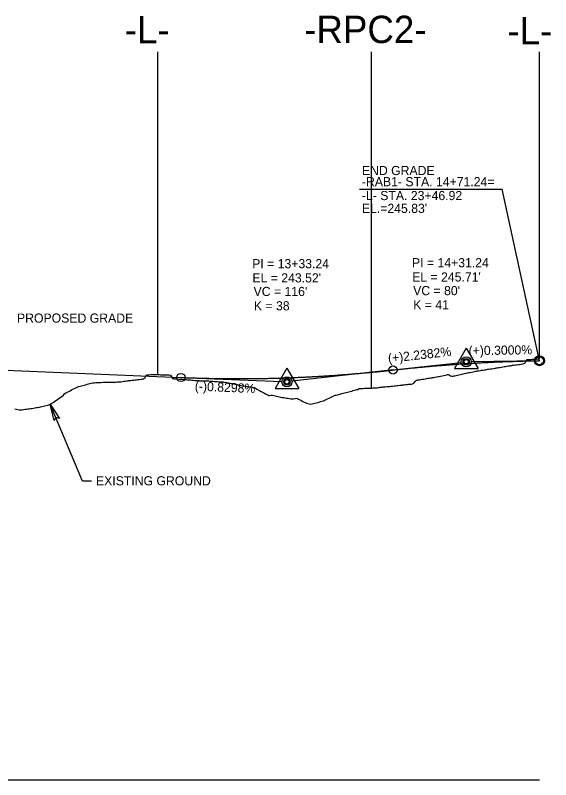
# Model space of a CAD drawing. Extents: x 2115752 to 2121174, y 562881 to 567245.
# Drawn here: x 2120307 to 2120599.7, y 565506.4 to 565924.5 of the extents above; entities that cross this region are included whole.
import ezdxf

# ---------------------------------------------------------------- set-up
doc = ezdxf.new("R2010")
doc.units = 0
for name, color, linetype in [('Exist Profile Cell', 7, 'Continuous'), ('Exist Vertical Profile Ground Line', 7, 'Continuous'), ('Prop PFL VPI Symbol CELL', 7, 'Continuous'), ('Prop Terminator CELL', 7, 'Continuous'), ('Prop Vertical Profile Curve Label', 7, 'Continuous'), ('Prop Vertical Profile Grade', 7, 'Continuous'), ('Prop Vertical Profile Grade Label', 7, 'Continuous'), ('Prop VPI Label', 7, 'Continuous'), ('Scratch_Level_1', 7, 'Continuous')]:
    doc.layers.add(name, color=color, linetype=linetype)

msp = doc.modelspace()

# ---------------------------------------------------------------- linework, layer by layer
at = {"layer": 'Exist Profile Cell'}
msp.add_line((2120122.31, 565506.42), (2120593.55, 565506.42), dxfattribs=at)
at = {"layer": 'Exist Vertical Profile Ground Line'}
for points in [[(2120553.44, 565728.76), (2120553.75, 565728.83), (2120554.21, 565728.91), (2120554.98, 565729.05), (2120555.75, 565729.19), (2120556.52, 565729.33), (2120557.29, 565729.5), (2120558.07, 565729.68), (2120558.9, 565729.84), (2120559.61, 565729.95), (2120560.38, 565730.07), (2120561.43, 565730.22), (2120561.92, 565730.31), (2120562.69, 565730.42), (2120563.46, 565730.54), (2120564.24, 565730.66), (2120565.19, 565730.85), (2120565.78, 565730.94), (2120566.67, 565731.08), (2120567.32, 565731.18), (2120568.38, 565731.33), (2120569.31, 565731.46), (2120569.64, 565731.51), (2120570, 565731.58), (2120570.41, 565731.64), (2120571.18, 565731.76), (2120571.95, 565731.88), (2120572.78, 565732.05), (2120573.49, 565732.17), (2120574.26, 565732.31), (2120575.07, 565732.45), (2120575.81, 565732.57), (2120576.58, 565732.7), (2120577.5, 565732.85), (2120578.12, 565732.94), (2120578.49, 565732.99), (2120578.89, 565733.04), (2120579.66, 565733.14), (2120580.43, 565733.23), (2120581.21, 565733.33), (2120582.12, 565733.45), (2120582.75, 565733.55), (2120583.52, 565733.67), (2120584.29, 565733.79), (2120584.64, 565733.85), (2120585.53, 565734.14), (2120585.83, 565734.62), (2120586.83, 565736.18), (2120587.38, 565736.21), (2120588.15, 565736.25), (2120588.92, 565736.29), (2120589.69, 565736.34), (2120590.46, 565736.38), (2120591.23, 565736.42), (2120592, 565736.46), (2120592.78, 565736.5), (2120593.55, 565736.54)], [(2120486.28, 565717.75), (2120487.05, 565717.95), (2120487.83, 565718.15), (2120488.6, 565718.35), (2120489.37, 565718.56), (2120490.15, 565718.77), (2120490.92, 565718.98), (2120491.7, 565719.19), (2120492.47, 565719.41), (2120493.24, 565719.63), (2120493.69, 565719.76), (2120494.02, 565719.9), (2120495.07, 565720.35), (2120495.57, 565720.38), (2120496.34, 565720.41), (2120497.11, 565720.44), (2120497.89, 565720.47), (2120498.9, 565720.52), (2120499.43, 565720.54), (2120499.84, 565720.56), (2120500.21, 565720.57), (2120500.64, 565720.57), (2120500.98, 565720.59), (2120501.84, 565720.63), (2120502.53, 565720.67), (2120503.55, 565720.73), (2120504.07, 565720.76), (2120504.84, 565720.82), (2120505.61, 565720.92), (2120506.08, 565720.98), (2120506.38, 565721.02), (2120507.16, 565721.13), (2120507.53, 565721.18), (2120507.93, 565721.21), (2120508.99, 565721.29), (2120509.47, 565721.32), (2120510.28, 565721.37), (2120511.01, 565721.44), (2120511.34, 565721.47), (2120511.78, 565721.51), (2120512.55, 565721.57), (2120512.99, 565721.61), (2120513.33, 565721.65), (2120514.1, 565721.74), (2120514.87, 565721.84), (2120515.79, 565721.95), (2120516.41, 565722.03), (2120517.18, 565722.12), (2120517.95, 565722.21), (2120518.31, 565722.26), (2120518.73, 565722.31), (2120519.55, 565722.42), (2120520.27, 565722.51), (2120521.11, 565722.6), (2120521.45, 565722.64), (2120521.81, 565722.67), (2120522.58, 565722.73), (2120523.61, 565722.82), (2120524.13, 565722.95), (2120524.9, 565723.27), (2120525.67, 565724.26), (2120526.44, 565724.96), (2120526.78, 565725.01), (2120527.21, 565725.07), (2120527.98, 565725.19), (2120528.75, 565725.31), (2120529.52, 565725.44), (2120530.3, 565725.56), (2120531.31, 565725.73), (2120531.84, 565725.81), (2120532.61, 565725.93), (2120533.38, 565726.05), (2120534.15, 565726.17), (2120534.92, 565726.29), (2120535.27, 565726.35), (2120535.7, 565726.42), (2120536.47, 565726.54), (2120537.24, 565726.69), (2120538.23, 565726.89), (2120538.78, 565726.99), (2120539.55, 565727.13), (2120540.32, 565727.3), (2120541.39, 565727.53), (2120542.13, 565727.7), (2120542.86, 565727.89), (2120543.41, 565728), (2120543.73, 565728.07), (2120544.38, 565727.7), (2120544.95, 565727.36), (2120545.72, 565727.09), (2120546.49, 565727.17), (2120546.91, 565727.27), (2120547.27, 565727.35), (2120548.04, 565727.52), (2120548.81, 565727.69), (2120549.58, 565727.87), (2120550.42, 565728.06), (2120551.26, 565728.26), (2120551.89, 565728.4), (2120552.67, 565728.58), (2120553.44, 565728.76)], [(2120340.08, 565720.75), (2120340.85, 565721.14), (2120341.63, 565721.5), (2120342.4, 565721.69), (2120343.17, 565721.88), (2120343.94, 565722.07), (2120344.72, 565722.26), (2120345.49, 565722.46), (2120346.26, 565722.65), (2120347.04, 565722.85), (2120347.81, 565723.04), (2120348.58, 565723.24), (2120349.43, 565723.46), (2120350.13, 565723.55), (2120351.07, 565723.6), (2120351.67, 565723.63), (2120352.45, 565723.66), (2120353.3, 565723.7), (2120353.99, 565723.72), (2120355.06, 565723.77), (2120355.54, 565723.78), (2120356.31, 565723.79), (2120357.14, 565723.8), (2120357.86, 565723.81), (2120358.73, 565723.83), (2120359.4, 565723.84), (2120360.18, 565723.86), (2120360.95, 565723.88), (2120361.72, 565723.89), (2120362.05, 565723.9), (2120362.79, 565723.93), (2120363.27, 565723.98), (2120364.04, 565724.04), (2120364.81, 565724.1), (2120365.59, 565724.21), (2120366.5, 565724.33), (2120367.13, 565724.41), (2120367.91, 565724.52), (2120368.68, 565724.63), (2120369.12, 565724.69), (2120369.52, 565724.75), (2120369.86, 565724.79), (2120370.22, 565724.82), (2120371, 565724.9), (2120371.77, 565724.97), (2120372.54, 565725.04), (2120373.32, 565725.12), (2120374.09, 565725.22), (2120374.86, 565725.32), (2120375.63, 565725.42), (2120376.41, 565725.53), (2120377.18, 565725.66), (2120378, 565726.45), (2120378.73, 565727.9), (2120379.5, 565727.91), (2120380.27, 565727.92), (2120381.05, 565727.94), (2120381.46, 565727.94), (2120381.82, 565727.95), (2120382.59, 565727.95), (2120383.36, 565727.96), (2120384.14, 565727.97), (2120385.18, 565727.99), (2120385.68, 565727.97), (2120386.46, 565727.93), (2120387.23, 565727.9), (2120388.29, 565727.86), (2120388.78, 565727.84), (2120389.55, 565727.81), (2120390.33, 565727.78), (2120391.1, 565727.76), (2120391.87, 565727.65), (2120393.03, 565725.8), (2120393.48, 565725.75), (2120393.81, 565725.73), (2120394.2, 565725.69), (2120394.97, 565725.63), (2120395.74, 565725.57), (2120396.52, 565725.51), (2120397.29, 565725.46), (2120398.06, 565725.4), (2120399.24, 565725.32), (2120399.61, 565725.3), (2120400.39, 565725.24), (2120401.16, 565725.19), (2120401.93, 565725.13), (2120402.87, 565725.04), (2120403.48, 565725), (2120404.3, 565724.93), (2120405.25, 565724.81), (2120406.26, 565724.71), (2120406.83, 565724.69), (2120407.35, 565724.67), (2120407.67, 565724.65), (2120408.12, 565724.62), (2120408.9, 565724.58), (2120409.67, 565724.54), (2120410.45, 565724.51), (2120411.22, 565724.47), (2120411.99, 565724.47), (2120412.77, 565724.47)], [(2120306.84, 565709.22), (2120307.62, 565709.07), (2120308.39, 565708.93), (2120309.16, 565708.79), (2120310.21, 565708.62), (2120310.71, 565708.7), (2120311.48, 565708.83), (2120312.36, 565708.98), (2120313.03, 565709.06), (2120313.8, 565709.16), (2120314.57, 565709.27), (2120315.35, 565709.38), (2120316.12, 565709.5), (2120316.89, 565709.62), (2120317.66, 565709.75), (2120318.44, 565709.89), (2120319.21, 565710.03), (2120319.98, 565710.18), (2120320.28, 565710.24), (2120320.76, 565710.34), (2120321.53, 565710.51), (2120322.3, 565710.69), (2120323.08, 565710.88), (2120323.85, 565711.07), (2120324.62, 565711.27), (2120325.39, 565711.47), (2120326.17, 565711.75), (2120326.94, 565712.26), (2120327.71, 565712.77), (2120328.49, 565713.29), (2120329.26, 565713.82), (2120330.03, 565714.35), (2120330.8, 565714.89), (2120331.58, 565715.44), (2120332.38, 565716.02), (2120333.12, 565716.62), (2120334.15, 565717.69), (2120334.67, 565718.03), (2120335.44, 565718.41), (2120336.22, 565718.8), (2120336.99, 565719.18), (2120337.76, 565719.57), (2120338.53, 565719.96), (2120339.31, 565720.35), (2120340.08, 565720.75)], [(2120412.77, 565724.47), (2120413.54, 565724.46), (2120414.47, 565724.37), (2120415.09, 565724.32), (2120415.86, 565724.26), (2120416.64, 565724.18), (2120416.99, 565724.14), (2120417.41, 565724.12), (2120418.18, 565724.07), (2120419.1, 565724.05), (2120420.05, 565724.01), (2120420.51, 565723.94), (2120420.82, 565723.89), (2120421.28, 565723.82), (2120422.05, 565723.69), (2120422.83, 565723.56), (2120423.75, 565723.4), (2120424.47, 565723.28), (2120425.2, 565723.13), (2120425.92, 565723.02), (2120427.06, 565722.82), (2120427.47, 565722.71), (2120427.82, 565722.62), (2120428.24, 565722.47), (2120429.02, 565722.21), (2120429.79, 565722.09), (2120430.56, 565721.97), (2120431.34, 565721.85), (2120432.11, 565721.74), (2120432.89, 565721.63), (2120433.66, 565721.52), (2120434.43, 565721.42), (2120435.21, 565721.32), (2120435.98, 565721.22), (2120436.76, 565721.13), (2120437.53, 565720.92), (2120438.3, 565720.5), (2120439.08, 565720.07), (2120439.85, 565719.64), (2120440.62, 565719.22), (2120441.4, 565718.8), (2120442.17, 565718.37), (2120442.95, 565717.95), (2120443.72, 565717.53), (2120444.49, 565717.11), (2120445.27, 565716.69), (2120445.59, 565716.51), (2120446.04, 565716.57), (2120446.81, 565716.68), (2120447.61, 565716.79), (2120448.36, 565716.6), (2120449.14, 565716.41), (2120449.91, 565716.22), (2120450.68, 565716.04), (2120451.46, 565715.86), (2120452.23, 565715.69), (2120453.01, 565715.52), (2120453.44, 565715.43), (2120453.78, 565715.37), (2120454.55, 565715.24), (2120455.33, 565715.11), (2120456.1, 565714.99), (2120456.87, 565714.87), (2120457.65, 565714.76), (2120458.42, 565714.65), (2120459.2, 565714.78), (2120459.97, 565714.91), (2120460.95, 565715.08), (2120461.52, 565714.77), (2120462.29, 565714.35), (2120463.07, 565713.93), (2120463.84, 565713.51), (2120464.61, 565713.09), (2120465.49, 565712.62), (2120466.16, 565712.42), (2120466.93, 565712.2), (2120467.71, 565711.99), (2120468.48, 565711.88), (2120469.26, 565711.98), (2120470.04, 565712.09), (2120470.8, 565712.29), (2120471.58, 565712.5), (2120472.35, 565712.72), (2120473.12, 565712.94), (2120473.9, 565713.17), (2120474.67, 565713.4), (2120475.45, 565713.64), (2120476.22, 565713.99), (2120476.99, 565714.34), (2120477.77, 565714.7), (2120478.54, 565715.06), (2120479.32, 565715.43), (2120480.09, 565715.81), (2120480.86, 565716.19), (2120481.83, 565716.67), (2120482.41, 565716.78), (2120483.18, 565716.94), (2120483.96, 565717.15), (2120484.93, 565717.42), (2120485.51, 565717.56), (2120486.28, 565717.75)]]:
    msp.add_lwpolyline(points, dxfattribs=at)
at = {"layer": 'Prop PFL VPI Symbol CELL'}
for p, q in [((2120553.54, 565742.45), (2120547.09, 565731.25)), ((2120553.54, 565742.45), (2120560.04, 565731.25)), ((2120455.54, 565731.48), (2120449.09, 565720.28)), ((2120455.54, 565731.48), (2120462.04, 565720.28)), ((2120547.09, 565731.25), (2120560.04, 565731.25)), ((2120449.09, 565720.28), (2120462.04, 565720.28))]:
    msp.add_line(p, q, dxfattribs=at)
for centre, radius in [((2120553.55, 565734.97), 1.75), ((2120553.55, 565734.97), 1.2), ((2120455.55, 565724), 1.75), ((2120455.55, 565724), 1.2)]:
    msp.add_circle(centre, radius, dxfattribs=at)
at = {"layer": 'Prop Terminator CELL'}
msp.add_lwpolyline([(2120328.2, 565702.85), (2120326.17, 565711.75), (2120331.13, 565704.01), (2120329.21, 565704.46)], close=True, dxfattribs=at)
at = {"layer": 'Prop Vertical Profile Curve Label'}
for centre in [(2120593.55, 565735.57), (2120513.55, 565730.49), (2120513.55, 565730.49), (2120397.55, 565726.4)]:
    msp.add_circle(centre, 2.25, dxfattribs=at)
at = {"layer": 'Prop Vertical Profile Grade'}
msp.add_line((2120202.31, 565734.51), (2120397.55, 565726.4), dxfattribs=at)
for points in [[(2120513.55, 565730.49), (2120515.15, 565730.67), (2120516.75, 565730.84), (2120518.35, 565731.01), (2120519.95, 565731.18), (2120521.55, 565731.35), (2120523.15, 565731.51), (2120524.75, 565731.67), (2120526.35, 565731.82), (2120527.95, 565731.97), (2120529.55, 565732.12), (2120531.15, 565732.27), (2120532.75, 565732.41), (2120534.35, 565732.55), (2120535.95, 565732.69), (2120537.55, 565732.83), (2120539.15, 565732.96), (2120540.75, 565733.08), (2120542.35, 565733.21), (2120543.95, 565733.33), (2120545.55, 565733.45), (2120547.15, 565733.57), (2120548.75, 565733.68), (2120550.35, 565733.79), (2120551.95, 565733.89), (2120553.55, 565734), (2120555.15, 565734.1), (2120556.75, 565734.19), (2120558.35, 565734.29), (2120559.95, 565734.38), (2120561.55, 565734.46), (2120563.15, 565734.55), (2120564.75, 565734.63), (2120566.35, 565734.71), (2120567.95, 565734.78), (2120569.55, 565734.86), (2120571.15, 565734.93), (2120572.75, 565734.99), (2120574.35, 565735.05), (2120575.95, 565735.11), (2120577.55, 565735.17), (2120579.15, 565735.22), (2120580.75, 565735.27), (2120582.35, 565735.32), (2120583.95, 565735.37), (2120585.55, 565735.41), (2120587.15, 565735.44), (2120588.75, 565735.48), (2120590.35, 565735.51), (2120591.95, 565735.54), (2120593.55, 565735.57)], [(2120397.55, 565726.4), (2120399.87, 565726.31), (2120402.19, 565726.23), (2120404.51, 565726.15), (2120406.83, 565726.08), (2120409.15, 565726.01), (2120411.47, 565725.96), (2120413.79, 565725.91), (2120416.11, 565725.86), (2120418.43, 565725.83), (2120420.75, 565725.8), (2120423.07, 565725.78), (2120425.39, 565725.76), (2120427.71, 565725.75), (2120430.03, 565725.75), (2120432.35, 565725.76), (2120434.67, 565725.78), (2120436.99, 565725.8), (2120439.31, 565725.82), (2120441.63, 565725.86), (2120443.95, 565725.9), (2120446.27, 565725.95), (2120448.59, 565726.01), (2120450.91, 565726.07), (2120453.23, 565726.14), (2120455.55, 565726.22), (2120457.87, 565726.31), (2120460.19, 565726.4), (2120462.51, 565726.5), (2120464.83, 565726.61), (2120467.15, 565726.72), (2120469.47, 565726.84), (2120471.79, 565726.97), (2120474.11, 565727.1), (2120476.43, 565727.25), (2120478.75, 565727.4), (2120481.07, 565727.55), (2120483.39, 565727.71), (2120485.71, 565727.89), (2120488.03, 565728.06), (2120490.35, 565728.25), (2120492.67, 565728.44), (2120494.99, 565728.64), (2120497.31, 565728.85), (2120499.63, 565729.06), (2120501.95, 565729.28), (2120504.27, 565729.51), (2120506.59, 565729.74), (2120508.91, 565729.98), (2120511.23, 565730.23), (2120513.55, 565730.49)]]:
    msp.add_spline(points, degree=3, dxfattribs=at)
at = {"layer": 'Prop VPI Label'}
for p, q in [((2120495.29, 565829.37), (2120573.27, 565829.37)), ((2120593.55, 565735.57), (2120573.27, 565829.37)), ((2120513.55, 565730.49), (2120550.82, 565734.66)), ((2120593.55, 565735.57), (2120556.3, 565735.01)), ((2120513.55, 565730.49), (2120458.28, 565724.3)), ((2120397.55, 565726.4), (2120452.8, 565724.11))]:
    msp.add_line(p, q, dxfattribs=at)
msp.add_lwpolyline([(2120348.7, 565669.62), (2120343.73, 565669.62), (2120326.17, 565711.75)], dxfattribs=at)
for centre in [(2120553.55, 565734.97), (2120593.55, 565735.57), (2120455.55, 565724)]:
    msp.add_circle(centre, 2.75, dxfattribs=at)
at = {"layer": 'Scratch_Level_1'}
for p, q in [((2120384.91, 565728), (2120384.91, 565904.4)), ((2120501.76, 565720.63), (2120501.76, 565904.4)), ((2120593.55, 565736.54), (2120593.55, 565904.4))]:
    msp.add_line(p, q, dxfattribs=at)

# ---------------------------------------------------------------- texts
at = {"layer": 'Prop Vertical Profile Curve Label'}
for s, p in [("VC = 116'", (2120437.29, 565770.94)), ("VC = 80'", (2120524.53, 565771.4)), ('K = 38', (2120437.47, 565763.1)), ('K = 41', (2120524.59, 565763.65))]:
    msp.add_text(s, height=5, dxfattribs=at).set_placement(p)
at = {"layer": 'Prop Vertical Profile Grade Label'}
for s, rotation, p in [('(+)2.2382%', 6.3853, (2120511.05, 565734.37)), ('(+)0.3000%', 0.8594, (2120554.88, 565738.56)), ('(-)0.8298%', 357.6241, (2120405.09, 565719.22))]:
    msp.add_text(s, height=5, rotation=rotation, dxfattribs=at).set_placement(p)
at = {"layer": 'Prop VPI Label'}
for s, p in [('END GRADE', (2120496.52, 565837.08)), ('-RAB1- STA. 14+71.24=', (2120496.52, 565830.98)), ('-L- STA. 23+46.92', (2120496.52, 565823.39)), ("EL.=245.83'", (2120496.52, 565816.39)), ('PI = 14+31.24', (2120523.89, 565786.66)), ('PI = 13+33.24', (2120436.53, 565786.13)), ("EL = 243.52'", (2120436.65, 565778.38)), ("EL = 245.71'", (2120524, 565778.86)), ('PROPOSED GRADE', (2120307.95, 565756.38)), ('EXISTING GROUND', (2120351.14, 565667.38))]:
    msp.add_text(s, height=5, dxfattribs=at).set_placement(p)
at = {"layer": 'Scratch_Level_1'}
for s, p in [('-L-', (2120366.91, 565909.08)), ('-RPC2-', (2120464.97, 565909.25)), ('-L-', (2120576.11, 565908.58))]:
    msp.add_text(s, height=15, dxfattribs=at).set_placement(p)

doc.saveas('drawing.dxf')
